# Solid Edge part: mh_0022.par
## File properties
Title: joint
Author: edge
Template: normal.par
Last saved by: edge
Revision: 30
Application: Solid Edge
Material: SWM-B
非切断部品: False
文書内容のタイプ: 0
Density: 0.007850 g/mm^3
Accuracy: 0.99
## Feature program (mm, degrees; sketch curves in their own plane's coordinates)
sketch for "unnamed Protrusion 1" plane through (0, 0, 0) normal (0, -1, 0) x-axis (1, 0, 0)
extrude "unnamed Protrusion 1" add finite 440 along -normal
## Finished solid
Body 1: solid body, 3 faces, 2 edges, 0 vertices.
  Faces by surface: plane 2, cylinder 1
  Edges by curve: circle 2
Bounding box of the edges (mm): 5.000 x 440.000 x 5.000, from (-2.5, 0, -2.5) to (2.5, 440, 2.5).
Cylindrical faces by radius (mm): R2.5 x1
Planar faces by outward normal: +y 1, -y 1
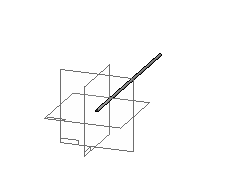
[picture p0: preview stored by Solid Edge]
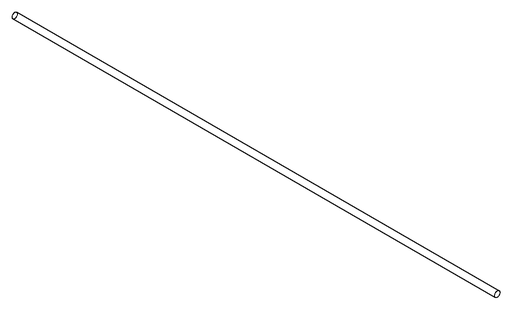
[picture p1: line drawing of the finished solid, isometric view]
